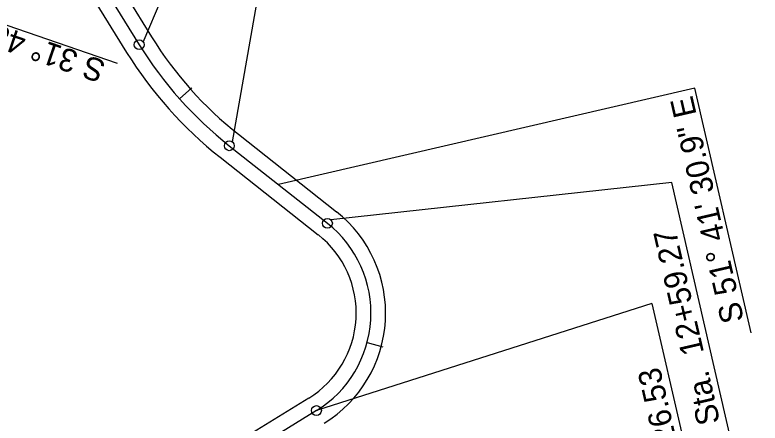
# Model space of a CAD drawing. Extents: x 472216 to 481979, y 489069 to 507339.
# Drawn here: x 481096.6 to 481324.6, y 492956.1 to 493080.9 of the extents above; entities that cross this region are included whole.
import ezdxf

# ---------------------------------------------------------------- set-up
doc = ezdxf.new("R2010")
doc.units = 0
for name, color, linetype in [('Old_Level_12', 7, 'Continuous'), ('Prop Drainage Structure Pipe RCP 24in Class III Label', 7, 'Continuous'), ('Sheet Block Revision CELL', 7, 'Continuous'), ('Sheet North Arrow Point CELL', 7, 'Continuous'), ('Sheet PE Seal Cell', 7, 'Continuous'), ('Sheet Plan And Profile CELL', 7, 'Continuous')]:
    doc.layers.add(name, color=color, linetype=linetype)

msp = doc.modelspace()

# ---------------------------------------------------------------- linework, layer by layer
at = {"layer": 'Old_Level_12'}
for p, q in [((481135.86, 493072.61), (481189.73, 493200.59)), ((481163.11, 493042.08), (481188.21, 493184.34)), ((481127.95, 493066.06), (481054.72, 493091.3)), ((481304.66, 493058.54), (481177.2, 493029.04)), ((481321.93, 492983.65), (481304.66, 493058.54)), ((481297.62, 493029.62), (481193.27, 493018.24)), ((481324.62, 492912.5), (481297.62, 493029.62)), ((481291.48, 492992.64), (481188.85, 492959.9)), ((481291.48, 492992.64), (481319.55, 492870.91))]:
    msp.add_line(p, q, dxfattribs=at)
for centre in [(481134.59, 493071.82), (481162.18, 493040.9), (481192.21, 493017.18), (481188.85, 492959.9)]:
    msp.add_circle(centre, 1.5, dxfattribs=at)
at = {"layer": 'Prop Drainage Structure Pipe RCP 24in Class III Label'}
for p, q in [((481068.01, 493187.73), (481138.41, 493074.2)), ((481060.36, 493182.99), (481130.76, 493069.45)), ((481164.97, 493044.43), (481195, 493020.71)), ((481159.4, 493037.37), (481189.42, 493013.65)), ((481186.49, 492963.73), (481145.21, 492938.34))]:
    msp.add_line(p, q, dxfattribs=at)
for centre, radius, start, end in [((481236.57, 493135.06), 115.5, 211.8022, 231.6919), ((481236.57, 493135.06), 124.5, 211.8022, 231.6919), ((481170.52, 492989.71), 39.5, 301.5898, 51.6919), ((481170.52, 492989.71), 30.5, 301.5898, 51.6919)]:
    msp.add_arc(centre, radius, start, end, dxfattribs=at)
at = {"layer": 'Sheet Block Revision CELL'}
for centre, start, end in [((480223.4, 492319.16), 28.33301, 49.09831), ((480214.14, 492312.08), 12.98112, 48.98584)]:
    msp.add_arc(centre, 1060, start, end, dxfattribs=at)
at = {"layer": 'Sheet North Arrow Point CELL'}
for p, q in [((481040.07, 493224.25), (481134.59, 493071.82)), ((481162.18, 493040.9), (481192.21, 493017.18)), ((481188.85, 492959.9), (481117.45, 492915.99))]:
    msp.add_line(p, q, dxfattribs=at)
for centre, radius, start, end in [((480155.89, 492286.67), 1060, 12.98112, 71.78843), ((480155.89, 492286.67), 1060, 12.98112, 71.78843), ((481236.57, 493135.06), 120, 211.8022, 231.6919), ((481170.52, 492989.71), 35, 301.5898, 51.6919)]:
    msp.add_arc(centre, radius, start, end, dxfattribs=at)
at = {"layer": 'Sheet PE Seal Cell'}
for p, q in [((481146.92, 493055.29), (481150.66, 493058.62)), ((481204.33, 492980.67), (481209.16, 492979.38))]:
    msp.add_line(p, q, dxfattribs=at)

# ---------------------------------------------------------------- texts
at = {"layer": 'Old_Level_12'}
for s, p in [('-DR7- PC Sta.  12+59.27', (481322.11, 492914.3)), ('-DR7- PT Sta.  13+26.53', (481317.08, 492872.88))]:
    msp.add_text(s, height=7, rotation=102.9811, dxfattribs=at).set_placement(p)
at = {"layer": 'Sheet Plan And Profile CELL'}
for s, rotation, p in [('S 31%%d 48\' 07.9" E', 160.9892, (481124.76, 493066.65)), ('S 51%%d 41\' 30.9" E', 102.9811, (481319.74, 492987.53))]:
    msp.add_text(s, height=7, rotation=rotation, dxfattribs=at).set_placement(p)

doc.saveas('drawing.dxf')
